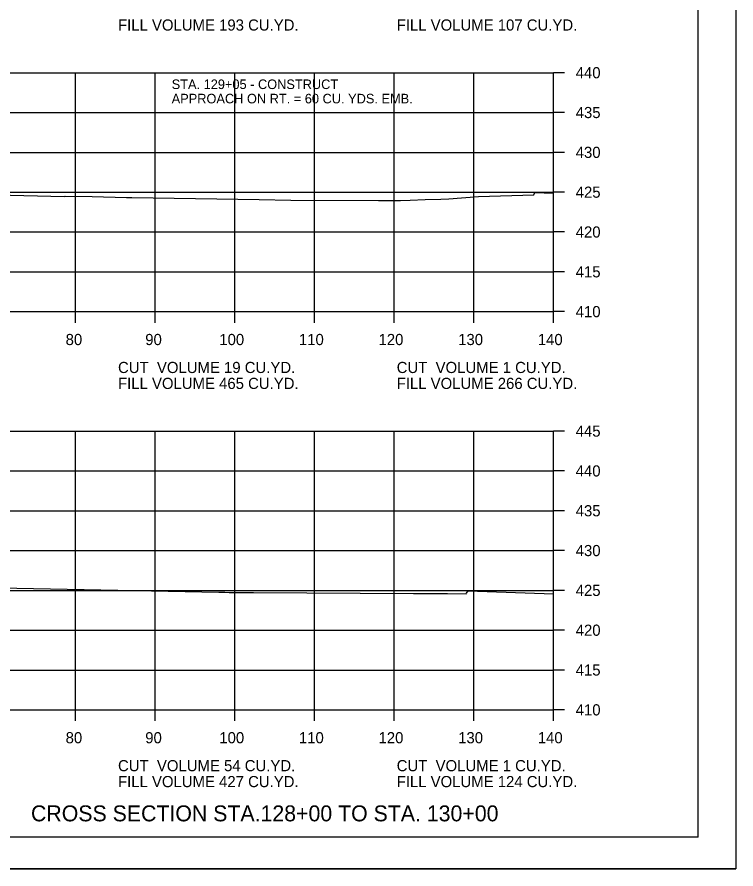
# Model space of a CAD drawing. Extents: x 1538688 to 1540766, y 656250 to 671912.
# Drawn here: x 1538930.8 to 1539021.1, y 660391.3 to 660498.3 of the extents above; entities that cross this region are included whole.
import ezdxf

# ---------------------------------------------------------------- set-up
doc = ezdxf.new("R2010")
doc.units = 0
for name, color, linetype in [('15', 7, 'Continuous'), ('18', 7, 'Continuous'), ('22', 7, 'Continuous'), ('26', 7, 'Continuous'), ('7', 7, 'Continuous'), ('Borings', 7, 'Continuous'), ('Horizontal Alignment', 7, 'Continuous'), ('RipRap', 7, 'Continuous')]:
    doc.layers.add(name, color=color, linetype=linetype)

msp = doc.modelspace()

# ---------------------------------------------------------------- linework, layer by layer
at = {"layer": '18'}
for points in [[(1538919.85, 660476.16), (1538936.73, 660475.77), (1538936.88, 660475.78), (1538940.26, 660475.76), (1538944.55, 660475.62), (1538945.22, 660475.62), (1538961.22, 660475.39), (1538965.19, 660475.3), (1538976.22, 660475.25), (1538978.99, 660475.26), (1538980.19, 660475.31), (1538982.07, 660475.38), (1538984.04, 660475.44), (1538985.06, 660475.47), (1538988.78, 660475.74), (1538995.72, 660475.98), (1538995.83, 660476.28), (1538998.18, 660476.16)], [(1538928.63, 660426.6), (1538956.16, 660426.07), (1538956.84, 660426.06), (1538956.91, 660426.06), (1538957.44, 660426.05), (1538960.5, 660426.02), (1538980.61, 660425.9), (1538984.86, 660425.89), (1538987.21, 660425.88), (1538987.27, 660425.96), (1538987.46, 660426.24), (1538998.18, 660425.87)]]:
    msp.add_lwpolyline(points, dxfattribs=at)
at = {"layer": '22'}
for p, q in [((1538718.18, 660491.3), (1538998.18, 660491.3)), ((1538938.18, 660461.3), (1538938.18, 660491.3)), ((1538948.18, 660461.3), (1538948.18, 660491.3)), ((1538958.18, 660461.3), (1538958.18, 660491.3)), ((1538968.18, 660461.3), (1538968.18, 660491.3)), ((1538978.18, 660461.3), (1538978.18, 660491.3)), ((1538988.18, 660461.3), (1538988.18, 660491.3)), ((1538998.18, 660461.3), (1538998.18, 660491.3)), ((1538718.18, 660486.3), (1538998.18, 660486.3)), ((1538718.18, 660481.3), (1538998.18, 660481.3)), ((1538718.18, 660476.3), (1538998.18, 660476.3)), ((1538718.18, 660471.3), (1538998.18, 660471.3)), ((1538718.18, 660466.3), (1538998.18, 660466.3)), ((1538718.18, 660461.3), (1538998.18, 660461.3)), ((1538718.18, 660446.3), (1538998.18, 660446.3)), ((1538938.18, 660411.3), (1538938.18, 660446.3)), ((1538948.18, 660411.3), (1538948.18, 660446.3)), ((1538958.18, 660411.3), (1538958.18, 660446.3)), ((1538968.18, 660411.3), (1538968.18, 660446.3)), ((1538978.18, 660411.3), (1538978.18, 660446.3)), ((1538988.18, 660411.3), (1538988.18, 660446.3)), ((1538998.18, 660411.3), (1538998.18, 660446.3)), ((1538718.18, 660441.3), (1538998.18, 660441.3)), ((1538718.18, 660436.3), (1538998.18, 660436.3)), ((1538718.18, 660431.3), (1538998.18, 660431.3)), ((1538718.18, 660426.3), (1538998.18, 660426.3)), ((1538718.18, 660421.3), (1538998.18, 660421.3)), ((1538718.18, 660416.3), (1538998.18, 660416.3)), ((1538718.18, 660411.3), (1538998.18, 660411.3))]:
    msp.add_line(p, q, dxfattribs=at)
at = {"layer": '26'}
msp.add_line((1538687.78, 660391.32), (1539021.11, 660391.32), dxfattribs=at)
msp.add_lwpolyline([(1538687.77, 660604.66), (1539021.11, 660604.66), (1539021.11, 660391.32), (1538687.77, 660391.32)], close=True, dxfattribs=at)
at = {"layer": 'Borings'}
for p, q in [((1538998.18, 660461.3), (1538998.18, 660491.3)), ((1538999.58, 660491.3), (1538998.18, 660491.3)), ((1538999.58, 660486.3), (1538998.18, 660486.3)), ((1538999.58, 660481.3), (1538998.18, 660481.3)), ((1538999.58, 660476.3), (1538998.18, 660476.3)), ((1538999.58, 660471.3), (1538998.18, 660471.3)), ((1538999.58, 660466.3), (1538998.18, 660466.3)), ((1538718.18, 660461.3), (1538998.18, 660461.3)), ((1538938.18, 660459.9), (1538938.18, 660461.3)), ((1538948.18, 660459.9), (1538948.18, 660461.3)), ((1538958.18, 660459.9), (1538958.18, 660461.3)), ((1538968.18, 660459.9), (1538968.18, 660461.3)), ((1538978.18, 660459.9), (1538978.18, 660461.3)), ((1538988.18, 660459.9), (1538988.18, 660461.3)), ((1538998.18, 660459.9), (1538998.18, 660461.3)), ((1538999.58, 660461.3), (1538998.18, 660461.3)), ((1538998.18, 660411.3), (1538998.18, 660446.3)), ((1538999.58, 660446.3), (1538998.18, 660446.3)), ((1538999.58, 660441.3), (1538998.18, 660441.3)), ((1538999.58, 660436.3), (1538998.18, 660436.3)), ((1538999.58, 660431.3), (1538998.18, 660431.3)), ((1538999.58, 660426.3), (1538998.18, 660426.3)), ((1538999.58, 660421.3), (1538998.18, 660421.3)), ((1538999.58, 660416.3), (1538998.18, 660416.3)), ((1538718.18, 660411.3), (1538998.18, 660411.3)), ((1538938.18, 660409.9), (1538938.18, 660411.3)), ((1538948.18, 660409.9), (1538948.18, 660411.3)), ((1538958.18, 660409.9), (1538958.18, 660411.3)), ((1538968.18, 660409.9), (1538968.18, 660411.3)), ((1538978.18, 660409.9), (1538978.18, 660411.3)), ((1538988.18, 660409.9), (1538988.18, 660411.3)), ((1538998.18, 660409.9), (1538998.18, 660411.3)), ((1538999.58, 660411.3), (1538998.18, 660411.3))]:
    msp.add_line(p, q, dxfattribs=at)
at = {"layer": 'RipRap'}
for q in [(1539016.36, 660600.76), (1538700.18, 660395.3)]:
    msp.add_line((1539016.36, 660395.3), q, dxfattribs=at)

# ---------------------------------------------------------------- texts
at = {"layer": '15'}
msp.add_text('CROSS SECTION STA.128+00 TO STA. 130+00', height=2, dxfattribs=at).set_placement((1538932.57, 660397.3))
at = {"layer": '7'}
for s, p in [('STA. 129+05 - CONSTRUCT', (1538950.24, 660489.25)), ('APPROACH ON RT. = 60 CU. YDS. EMB.', (1538950.24, 660487.45))]:
    msp.add_text(s, height=1.2, dxfattribs=at).set_placement(p)
at = {"layer": 'Horizontal Alignment'}
for s, p in [('FILL VOLUME 193 CU.YD.', (1538943.5, 660496.59)), ('FILL VOLUME 107 CU.YD.', (1538978.5, 660496.59)), ('440', (1539000.98, 660490.6)), ('435', (1539000.98, 660485.6)), ('430', (1539000.98, 660480.6)), ('425', (1539000.98, 660475.6)), ('420', (1539000.98, 660470.6)), ('415', (1539000.98, 660465.6)), ('410', (1539000.98, 660460.6)), ('80', (1538936.92, 660457.1)), ('90', (1538946.92, 660457.1)), ('100', (1538956.22, 660457.1)), ('110', (1538966.22, 660457.1)), ('120', (1538976.22, 660457.1)), ('130', (1538986.22, 660457.1)), ('140', (1538996.22, 660457.1)), ('CUT  VOLUME 19 CU.YD.', (1538943.5, 660453.59)), ('CUT  VOLUME 1 CU.YD.', (1538978.5, 660453.59)), ('FILL VOLUME 465 CU.YD.', (1538943.5, 660451.59)), ('FILL VOLUME 266 CU.YD.', (1538978.5, 660451.59)), ('445', (1539000.98, 660445.6)), ('440', (1539000.98, 660440.6)), ('435', (1539000.98, 660435.6)), ('430', (1539000.98, 660430.6)), ('425', (1539000.98, 660425.6)), ('420', (1539000.98, 660420.6)), ('415', (1539000.98, 660415.6)), ('410', (1539000.98, 660410.6)), ('80', (1538936.92, 660407.1)), ('90', (1538946.92, 660407.1)), ('100', (1538956.22, 660407.1)), ('110', (1538966.22, 660407.1)), ('120', (1538976.22, 660407.1)), ('130', (1538986.22, 660407.1)), ('140', (1538996.22, 660407.1)), ('CUT  VOLUME 54 CU.YD.', (1538943.5, 660403.59)), ('CUT  VOLUME 1 CU.YD.', (1538978.5, 660403.59)), ('FILL VOLUME 427 CU.YD.', (1538943.5, 660401.59)), ('FILL VOLUME 124 CU.YD.', (1538978.5, 660401.59))]:
    msp.add_text(s, height=1.4, dxfattribs=at).set_placement(p)

doc.saveas('drawing.dxf')
